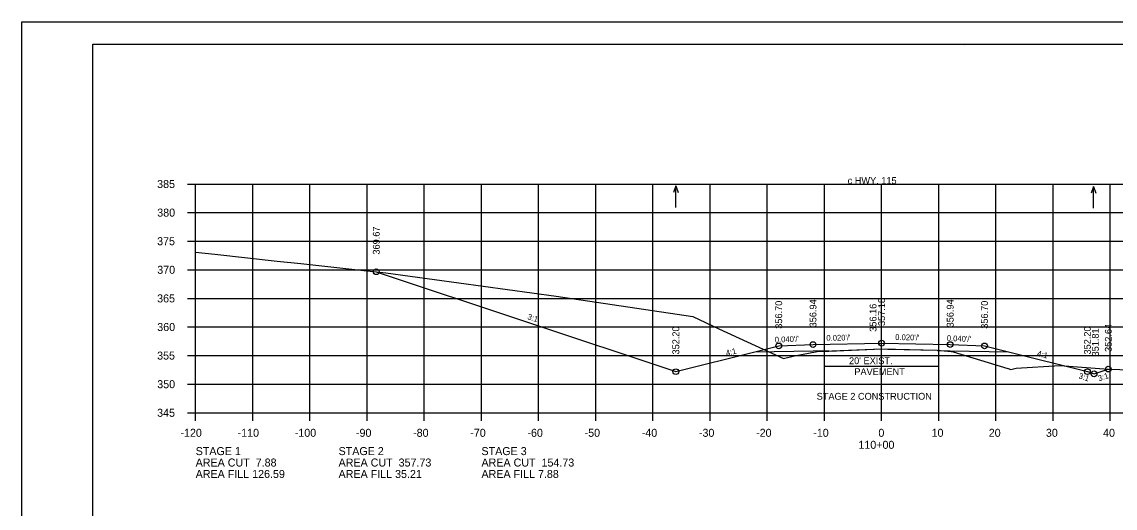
# Model space of a CAD drawing. Extents: x 1630712 to 1632516, y 782146 to 785403.
# Drawn here: x 1632182.6 to 1632373.8, y 784038.3 to 784123.3 of the extents above; entities that cross this region are included whole.
import ezdxf

# ---------------------------------------------------------------- set-up
doc = ezdxf.new("R2010")
doc.units = 0
for name, color, linetype in [('Notes', 7, 'Continuous'), ('R_Alt Surface', 7, 'Continuous'), ('R_Axis', 7, 'Continuous'), ('R_Axis Annot', 7, 'Continuous'), ('R_Border', 7, 'Continuous'), ('R_Exist Surface', 7, 'Continuous'), ('R_Fin Surface', 7, 'Continuous'), ('R_Grid', 7, 'Continuous'), ('R_No Plot', 7, 'Continuous'), ('R_Water Annot', 7, 'Continuous'), ('R_Xsect Elev', 7, 'Continuous'), ('R_Xsect Slope', 7, 'Continuous')]:
    doc.layers.add(name, color=color, linetype=linetype)

msp = doc.modelspace()

# ---------------------------------------------------------------- linework, layer by layer
at = {"layer": 'Notes'}
for p, q in [((1632322.96, 784061.4), (1632322.96, 784064.8)), ((1632322.96, 784063.1), (1632342.96, 784063.1)), ((1632342.96, 784061.4), (1632342.96, 784064.8))]:
    msp.add_line(p, q, dxfattribs=at)
at = {"layer": 'R_Alt Surface'}
msp.add_lwpolyline([(1632310.79, 784065.61), (1632320.96, 784065.81), (1632323.67, 784065.86), (1632323.72, 784065.76), (1632332.97, 784066.12), (1632342.7, 784065.88), (1632342.75, 784065.86), (1632344.96, 784065.81), (1632355.14, 784065.61)], dxfattribs=at)
at = {"layer": 'R_Axis'}
for p, q in [((1632211.56, 784094.96), (1632212.96, 784094.96)), ((1632212.96, 784054.96), (1632212.96, 784094.96)), ((1632211.56, 784089.96), (1632212.96, 784089.96)), ((1632211.56, 784084.96), (1632212.96, 784084.96)), ((1632211.56, 784079.96), (1632212.96, 784079.96)), ((1632211.56, 784074.96), (1632212.96, 784074.96)), ((1632211.56, 784069.96), (1632212.96, 784069.96)), ((1632211.56, 784064.96), (1632212.96, 784064.96)), ((1632211.56, 784059.96), (1632212.96, 784059.96)), ((1632211.56, 784054.96), (1632212.96, 784054.96)), ((1632212.96, 784054.96), (1632492.96, 784054.96)), ((1632212.96, 784053.56), (1632212.96, 784054.96)), ((1632222.96, 784053.56), (1632222.96, 784054.96)), ((1632232.96, 784053.56), (1632232.96, 784054.96)), ((1632242.96, 784053.56), (1632242.96, 784054.96)), ((1632252.96, 784053.56), (1632252.96, 784054.96)), ((1632262.96, 784053.56), (1632262.96, 784054.96)), ((1632272.96, 784053.56), (1632272.96, 784054.96)), ((1632282.96, 784053.56), (1632282.96, 784054.96)), ((1632292.96, 784053.56), (1632292.96, 784054.96)), ((1632302.96, 784053.56), (1632302.96, 784054.96)), ((1632312.96, 784053.56), (1632312.96, 784054.96)), ((1632322.96, 784053.56), (1632322.96, 784054.96)), ((1632332.96, 784053.56), (1632332.96, 784054.96)), ((1632342.96, 784053.56), (1632342.96, 784054.96)), ((1632352.96, 784053.56), (1632352.96, 784054.96)), ((1632362.96, 784053.56), (1632362.96, 784054.96)), ((1632372.96, 784053.56), (1632372.96, 784054.96))]:
    msp.add_line(p, q, dxfattribs=at)
at = {"layer": 'R_Border'}
for p, q in [((1632194.96, 784119.42), (1632511.14, 784119.42)), ((1632194.96, 783913.96), (1632194.96, 784119.42)), ((1632347.48, 784119.16), (1632347.48, 784119.16)), ((1632347.48, 784119.16), (1632347.48, 784119.16))]:
    msp.add_line(p, q, dxfattribs=at)
at = {"layer": 'R_Exist Surface'}
msp.add_lwpolyline([(1632212.96, 784083.03), (1632216.32, 784082.67), (1632227.23, 784081.49), (1632231.37, 784081.04), (1632242.37, 784079.86), (1632246.25, 784079.44), (1632276.04, 784075.37), (1632299.91, 784071.82), (1632304.47, 784069.64), (1632315.8, 784064.47), (1632317.71, 784064.89), (1632321.66, 784065.68), (1632323.48, 784065.75), (1632323.72, 784065.76), (1632324.24, 784065.78), (1632332.97, 784066.12), (1632334.05, 784066.09), (1632342.7, 784065.88), (1632345.15, 784065.65), (1632345.47, 784065.61), (1632355.05, 784062.7), (1632355.12, 784062.69), (1632355.56, 784062.54), (1632356.52, 784062.74), (1632364.13, 784063.22), (1632372.65, 784062.59), (1632380.58, 784062.33)], dxfattribs=at)
at = {"layer": 'R_Fin Surface'}
msp.add_lwpolyline([(1632244.56, 784079.62), (1632296.96, 784062.15), (1632310.79, 784065.61), (1632314.96, 784066.65), (1632320.96, 784066.89), (1632332.96, 784067.13), (1632344.96, 784066.89), (1632350.96, 784066.65), (1632355.14, 784065.61), (1632368.96, 784062.15), (1632370.13, 784061.77), (1632372.62, 784062.6)], dxfattribs=at)
at = {"layer": 'R_Grid'}
for p, q in [((1632212.96, 784094.96), (1632492.96, 784094.96)), ((1632212.96, 784054.96), (1632212.96, 784094.96)), ((1632222.96, 784054.96), (1632222.96, 784094.96)), ((1632232.96, 784054.96), (1632232.96, 784094.96)), ((1632242.96, 784054.96), (1632242.96, 784094.96)), ((1632252.96, 784054.96), (1632252.96, 784094.96)), ((1632262.96, 784054.96), (1632262.96, 784094.96)), ((1632272.96, 784054.96), (1632272.96, 784094.96)), ((1632282.96, 784054.96), (1632282.96, 784094.96)), ((1632292.96, 784054.96), (1632292.96, 784094.96)), ((1632302.96, 784054.96), (1632302.96, 784094.96)), ((1632312.96, 784054.96), (1632312.96, 784094.96)), ((1632322.96, 784054.96), (1632322.96, 784094.96)), ((1632332.96, 784054.96), (1632332.96, 784094.96)), ((1632342.96, 784054.96), (1632342.96, 784094.96)), ((1632352.96, 784054.96), (1632352.96, 784094.96)), ((1632362.96, 784054.96), (1632362.96, 784094.96)), ((1632372.96, 784054.96), (1632372.96, 784094.96)), ((1632212.96, 784089.96), (1632492.96, 784089.96)), ((1632212.96, 784084.96), (1632492.96, 784084.96)), ((1632212.96, 784079.96), (1632492.96, 784079.96)), ((1632212.96, 784074.96), (1632492.96, 784074.96)), ((1632212.96, 784069.96), (1632492.96, 784069.96)), ((1632212.96, 784064.96), (1632492.96, 784064.96)), ((1632212.96, 784059.96), (1632492.96, 784059.96)), ((1632212.96, 784054.96), (1632492.96, 784054.96))]:
    msp.add_line(p, q, dxfattribs=at)
at = {"layer": 'R_No Plot'}
msp.add_line((1632182.56, 784123.31), (1632515.9, 784123.31), dxfattribs=at)
msp.add_lwpolyline([(1632182.56, 784123.31), (1632515.9, 784123.31), (1632515.9, 783909.97), (1632182.56, 783909.97)], close=True, dxfattribs=at)
for centre in [(1632244.56, 784079.62), (1632314.96, 784066.65), (1632320.96, 784066.89), (1632332.96, 784067.13), (1632344.96, 784066.89), (1632350.96, 784066.65), (1632372.62, 784062.6), (1632296.96, 784062.15), (1632296.96, 784062.15), (1632368.96, 784062.15), (1632370.13, 784061.77)]:
    msp.add_circle(centre, 0.5, dxfattribs=at)
at = {"layer": 'R_Water Annot'}
for p, q in [((1632296.96, 784094.64), (1632296.54, 784093.49)), ((1632296.96, 784090.87), (1632296.96, 784094.64)), ((1632296.96, 784094.64), (1632297.38, 784093.49)), ((1632370.03, 784094.52), (1632369.61, 784093.36)), ((1632370.03, 784090.75), (1632370.03, 784094.52)), ((1632370.03, 784094.52), (1632370.45, 784093.36))]:
    msp.add_line(p, q, dxfattribs=at)

# ---------------------------------------------------------------- texts
at = {"layer": 'Notes'}
for s, p in [('c HWY. 115', (1632327.02, 784094.96)), ("20' EXIST.", (1632327.26, 784063.46)), ('PAVEMENT', (1632328.19, 784061.54)), ('STAGE 2 CONSTRUCTION', (1632321.6, 784057.24))]:
    msp.add_text(s, height=1.2, dxfattribs=at).set_placement(p)
at = {"layer": 'R_Axis'}
msp.add_text('-', height=0.0001, dxfattribs=at).set_placement((1632212.96, 784054.96))
at = {"layer": 'R_Axis Annot'}
for s, p in [('385', (1632206.22, 784094.26)), ('380', (1632206.24, 784089.26)), ('375', (1632206.22, 784084.26)), ('370', (1632206.24, 784079.26)), ('365', (1632206.22, 784074.26)), ('360', (1632206.24, 784069.26)), ('355', (1632206.22, 784064.26)), ('350', (1632206.24, 784059.26)), ('345', (1632206.22, 784054.26)), ('-120', (1632210.3, 784050.76)), ('-110', (1632220.3, 784050.76)), ('-100', (1632230.3, 784050.76)), ('-90', (1632241, 784050.76)), ('-80', (1632251, 784050.76)), ('-70', (1632261, 784050.76)), ('-60', (1632271, 784050.76)), ('-50', (1632281, 784050.76)), ('-40', (1632291, 784050.76)), ('-30', (1632301, 784050.76)), ('-20', (1632311, 784050.76)), ('-10', (1632321, 784050.76)), ('0', (1632332.4, 784050.76)), ('10', (1632341.7, 784050.76)), ('20', (1632351.7, 784050.76)), ('30', (1632361.7, 784050.76)), ('40', (1632371.7, 784050.76)), ('110+00', (1632328.9, 784048.66)), ('STAGE 1', (1632212.96, 784047.56)), ('STAGE 2', (1632237.96, 784047.56)), ('STAGE 3', (1632262.96, 784047.56)), ('AREA CUT  7.88', (1632212.96, 784045.56)), ('AREA CUT  357.73', (1632237.96, 784045.56)), ('AREA CUT  154.73', (1632262.96, 784045.56)), ('AREA FILL 126.59', (1632212.96, 784043.56)), ('AREA FILL 35.21', (1632237.96, 784043.56)), ('AREA FILL 7.88', (1632262.96, 784043.56))]:
    msp.add_text(s, height=1.4, dxfattribs=at).set_placement(p)
at = {"layer": 'R_Xsect Elev'}
for s, p in [('369.67', (1632245.16, 784082.62)), ('356.94', (1632321.56, 784069.89)), ('357.18', (1632333.56, 784070.13)), ('356.94', (1632345.56, 784069.89)), ('356.70', (1632315.56, 784069.65)), ('356.16', (1632332.06, 784069.12)), ('356.70', (1632351.56, 784069.65)), ('352.20', (1632297.56, 784065.15)), ('352.20', (1632369.56, 784065.15)), ('351.81', (1632370.96, 784064.81)), ('352.64', (1632373.22, 784065.6))]:
    msp.add_text(s, height=1.2, rotation=90, dxfattribs=at).set_placement(p)
at = {"layer": 'R_Xsect Slope'}
for s, rotation, p in [('3:1', 341.5651, (1632270.92, 784071.36)), ("0.040'/'", 2.2906, (1632314.29, 784067.23)), ("0.020'/'", 1.1458, (1632323.3, 784067.54)), ("0.020'/'", 358.8542, (1632335.33, 784067.69)), ("0.040'/'", 357.7094, (1632344.34, 784067.52)), ('4:1', 14.0362, (1632305.84, 784064.89)), ('4:1', 345.9638, (1632360.09, 784064.89)), ('3:1', 341.5651, (1632367.34, 784061.01)), ('3:1', 18.4349, (1632371.01, 784060.46))]:
    msp.add_text(s, height=1, rotation=rotation, dxfattribs=at).set_placement(p)

doc.saveas('drawing.dxf')
